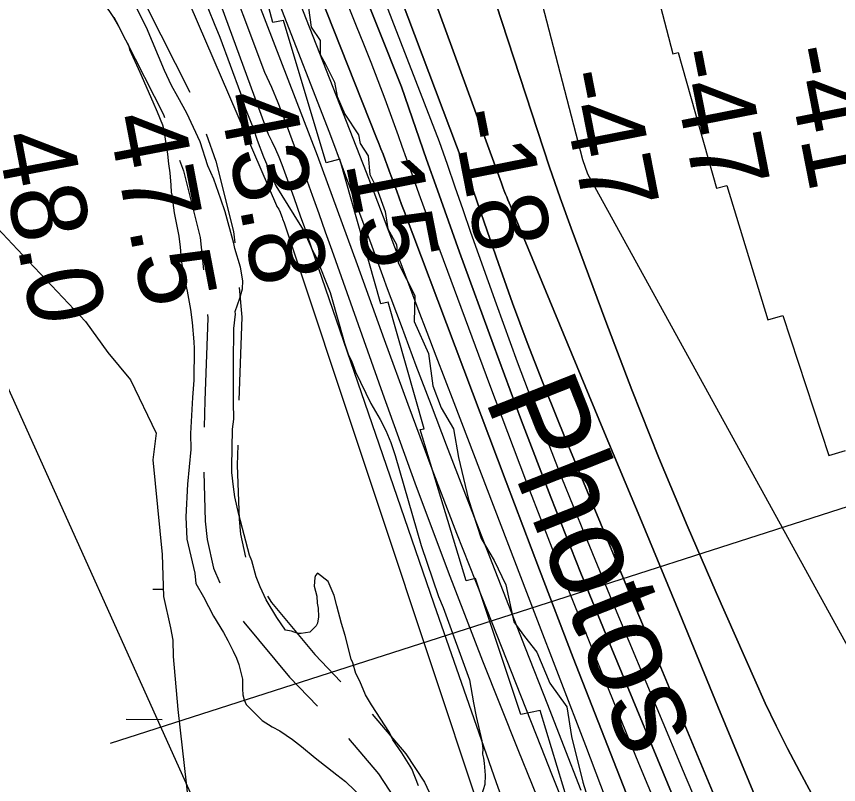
# Model space of a CAD drawing. Extents: x 3161665 to 3199565, y 885729 to 911164.
# Drawn here: x 3176382 to 3177112, y 893014 to 893695 of the extents above; entities that cross this region are included whole.
import ezdxf

# ---------------------------------------------------------------- set-up
doc = ezdxf.new("R2010")
doc.units = 0
for name, color, linetype in [('V-RIVR-EDGE', 7, 'Continuous'), ('V-RIVR-IDEN', 7, 'Continuous'), ('V-RIVR-RANG', 7, 'Continuous'), ('V-ROAD-CNTR', 7, 'Continuous'), ('V-RRAP-RVMT', 7, 'Continuous'), ('V-SITE-VEGE', 7, 'Continuous'), ('V-TOPO-DPTH', 7, 'Continuous'), ('V-TOPO-MAJR', 7, 'Continuous'), ('V-TOPO-MINR', 7, 'Continuous'), ('V-TOPO-WATR', 7, 'Continuous'), ('V-WETL-SWMP', 7, 'Continuous')]:
    doc.layers.add(name, color=color, linetype=linetype)

msp = doc.modelspace()

# ---------------------------------------------------------------- linework, layer by layer
at = {"layer": 'V-RIVR-EDGE'}
msp.add_lwpolyline([(3176641.22, 893703.05), (3176643.57, 893685.88), (3176651.64, 893673.94), (3176651.61, 893661.54), (3176656.36, 893652.94), (3176664.43, 893637.19), (3176666.78, 893624.31), (3176673.42, 893608.55), (3176685.77, 893590.4), (3176687.18, 893582.77), (3176694.31, 893571.78), (3176695.7, 893555.09), (3176701.87, 893542.67), (3176709.45, 893522.15), (3176711.79, 893506.88), (3176719.39, 893493.04), (3176720.78, 893476.82), (3176735.49, 893447.69), (3176734.96, 893424.8), (3176747.76, 893396.16), (3176751.51, 893367.54), (3176759.09, 893347.97), (3176770.01, 893329.34), (3176774.24, 893304.06), (3176783.21, 893266.84), (3176794.57, 893232), (3176805.96, 893212.42), (3176816.4, 893190.93), (3176823.47, 893158.01), (3176832.98, 893145.11), (3176843.91, 893131.26), (3176855.29, 893103.57), (3176870.5, 893082.55), (3176874.72, 893056.31), (3176884.64, 893015.75), (3176892.68, 892989.98)], dxfattribs=at)
at = {"layer": 'V-RIVR-RANG'}
msp.add_line((3176465.71, 893050.35), (3177322.46, 893325.99), dxfattribs=at)
at = {"layer": 'V-ROAD-CNTR'}
for points in [[(3176490.46, 893717.29), (3176497.28, 893704.73), (3176536, 893628.32)], [(3176468.49, 893694.88), (3176470.71, 893690.79), (3176512.52, 893608.28), (3176513.47, 893605.64)], [(3176550.51, 893591.11), (3176559.12, 893566.98), (3176574.75, 893504.51), (3176575.83, 893494.59)], [(3176526.91, 893567.97), (3176530.38, 893558.27), (3176545.14, 893499.22), (3176548.27, 893470.56)], [(3176579.84, 893454.8), (3176582.13, 893428.5), (3176579.4, 893354.96)], [(3176551.82, 893430.74), (3176552.08, 893427.75), (3176549.36, 893354.42), (3176548.85, 893330.81)], [(3176578.52, 893314.97), (3176578.14, 893297.13), (3176579.7, 893249.37), (3176581.09, 893235.88), (3176585.5, 893215.54)], [(3176548.33, 893290.82), (3176549.75, 893247.34), (3176551.42, 893231.16), (3176556.95, 893205.64), (3176562.57, 893192.69)], [(3176605.04, 893180.76), (3176608.36, 893175.39), (3176646.8, 893129.08), (3176670.09, 893105.02)], [(3176583.47, 893158.6), (3176583.94, 893157.83), (3176624.44, 893109.04), (3176649.26, 893083.4)], [(3176697.8, 893076.18), (3176727.62, 893041.12), (3176744.11, 893015.76), (3176754.36, 892994.38)], [(3176676.87, 893054.48), (3176703.52, 893023.14), (3176717.91, 893001.04), (3176731.94, 892971.75)]]:
    msp.add_lwpolyline(points, dxfattribs=at)
at = {"layer": 'V-RRAP-RVMT'}
for p, q in [((3176609.54, 893690.09), (3176577.55, 893814.21)), ((3176933.46, 893783), (3176964.43, 893662.23)), ((3176619.1, 893691.86), (3176609.54, 893690.09)), ((3176656.87, 893565.36), (3176619.1, 893691.86)), ((3176964.43, 893662.23), (3176969.2, 893663.46)), ((3176969.2, 893663.46), (3177003.33, 893543.13)), ((3176669.2, 893568.67), (3176656.87, 893565.36)), ((3176705.58, 893440.31), (3176669.2, 893568.67)), ((3177003.33, 893543.13), (3177012.55, 893545.5)), ((3177012.55, 893545.5), (3177048.64, 893426.23)), ((3176711.88, 893441.97), (3176705.58, 893440.31)), ((3176743.89, 893329.53), (3176711.88, 893441.97)), ((3177048.64, 893426.23), (3177061.99, 893429.92)), ((3177061.99, 893429.92), (3177103.02, 893305.7)), ((3176740.38, 893328.74), (3176743.89, 893329.53)), ((3176781.18, 893194.51), (3176740.38, 893328.74)), ((3177103.02, 893305.7), (3177117.64, 893310.16)), ((3176789.44, 893196.61), (3176781.18, 893194.51)), ((3176829.6, 893075.78), (3176789.44, 893196.61)), ((3176846.75, 893079.56), (3176829.6, 893075.78)), ((3176884.23, 892956.27), (3176846.75, 893079.56))]:
    msp.add_line(p, q, dxfattribs=at)
at = {"layer": 'V-SITE-VEGE'}
for p, q in [((3176459.68, 893707.05), (3176468.34, 893694.32)), ((3176468.34, 893694.32), (3176472.72, 893686.83)), ((3176472.72, 893686.83), (3176477.66, 893676.65)), ((3176477.66, 893676.65), (3176481.55, 893670.04)), ((3176481.55, 893670.04), (3176482.62, 893666.03)), ((3176482.62, 893666.03), (3176491.59, 893646.09)), ((3176491.59, 893646.09), (3176503.08, 893619.49)), ((3176503.08, 893619.49), (3176507.07, 893610.62)), ((3176507.07, 893610.62), (3176511.62, 893599.08)), ((3176511.62, 893599.08), (3176512.65, 893595.96)), ((3176512.65, 893595.96), (3176516.32, 893573.09)), ((3176516.32, 893573.09), (3176517.13, 893564.55)), ((3176517.13, 893564.55), (3176518.37, 893556.47)), ((3176518.37, 893556.47), (3176519.28, 893545.68)), ((3176519.28, 893545.68), (3176519.55, 893539.37)), ((3176519.55, 893539.37), (3176520.11, 893536.68)), ((3176520.11, 893536.68), (3176522.12, 893520.97)), ((3176522.12, 893520.97), (3176526.15, 893500.37)), ((3176526.15, 893500.37), (3176527.47, 893490.49)), ((3176527.47, 893490.49), (3176527.6, 893487.34)), ((3176527.6, 893487.34), (3176528.39, 893479.24)), ((3176528.39, 893479.24), (3176530.8, 893464.9)), ((3176530.8, 893464.9), (3176533.62, 893451.48)), ((3176533.62, 893451.48), (3176536.56, 893435.35)), ((3176536.56, 893435.35), (3176537.95, 893423.67)), ((3176537.95, 893423.67), (3176539.57, 893406.58)), ((3176539.57, 893406.58), (3176539.82, 893400.72)), ((3176539.82, 893400.72), (3176539.64, 893372.73)), ((3176539.64, 893372.73), (3176538.48, 893357.33)), ((3176538.48, 893357.33), (3176536.67, 893325.2)), ((3176536.67, 893325.2), (3176536.81, 893311.21)), ((3176536.81, 893311.21), (3176534.04, 893280.39)), ((3176534.04, 893280.39), (3176532.55, 893251.44)), ((3176532.55, 893251.44), (3176533.38, 893231.61)), ((3176533.38, 893231.61), (3176540.53, 893201.21)), ((3176540.53, 893201.21), (3176541.36, 893192.22)), ((3176541.36, 893192.22), (3176548.18, 893180.32)), ((3176548.18, 893180.32), (3176557.03, 893163.08)), ((3176557.03, 893163.08), (3176565.76, 893148.55)), ((3176565.76, 893148.55), (3176569.67, 893141.49)), ((3176569.67, 893141.49), (3176574.58, 893132.22)), ((3176574.58, 893132.22), (3176577.55, 893126.02)), ((3176577.55, 893126.02), (3176579.59, 893120.24)), ((3176579.59, 893120.24), (3176582.85, 893107.28)), ((3176582.85, 893107.28), (3176582.76, 893098.7)), ((3176582.76, 893098.7), (3176582.98, 893093.29)), ((3176582.98, 893093.29), (3176584.07, 893088.83)), ((3176584.07, 893088.83), (3176586.04, 893084.85)), ((3176586.04, 893084.85), (3176600.19, 893070.54)), ((3176600.19, 893070.54), (3176609, 893065.04)), ((3176609, 893065.04), (3176615.93, 893061.27)), ((3176615.93, 893061.27), (3176627.09, 893053.61)), ((3176627.09, 893053.61), (3176635.01, 893047.63)), ((3176635.01, 893047.63), (3176647.18, 893037.3)), ((3176647.18, 893037.3), (3176666.32, 893022.31)), ((3176666.32, 893022.31), (3176674.25, 893016.32)), ((3176674.25, 893016.32), (3176690.25, 893000.74))]:
    msp.add_line(p, q, dxfattribs=at)
for points in [[(3176574.78, 893352.98), (3176574.75, 893396.77), (3176575.12, 893409.43), (3176575.19, 893418.46), (3176576.46, 893431.15), (3176576.37, 893433.41), (3176580.38, 893445.31), (3176582.74, 893453.54), (3176582.89, 893460.77), (3176581.03, 893472.88), (3176575.82, 893489.36), (3176575.18, 893493.85), (3176567.23, 893521.96), (3176563.6, 893533.09), (3176557.43, 893550.89), (3176551.97, 893562.85), (3176545.2, 893584.24), (3176533.3, 893609.47), (3176525.47, 893624.04), (3176519.62, 893634.17), (3176513.65, 893647.47), (3176497.6, 893685.62), (3176495.16, 893690.03), (3176482.79, 893715.69)], [(3176547.41, 893714.34), (3176557.5, 893689.04), (3176562.52, 893677.06), (3176580.86, 893627.27), (3176585.5, 893613.47), (3176592.57, 893595.71), (3176595.71, 893585.45), (3176601.29, 893570.79), (3176612.3, 893545.07), (3176633.61, 893510.75), (3176637.01, 893505.03), (3176644.96, 893487.75), (3176647.89, 893482.46), (3176660.52, 893450.49), (3176668.47, 893422.38), (3176673.25, 893405.43), (3176676.86, 893394.74), (3176679.32, 893389.88), (3176682.89, 893380.1), (3176696.72, 893351.79), (3176704.99, 893337.69), (3176709.91, 893327.96), (3176714.42, 893317.32), (3176718.07, 893305.73), (3176741.29, 893225.9), (3176756.74, 893180.5), (3176760.76, 893170.74), (3176784.22, 893106.72), (3176787.79, 893086.1), (3176790.1, 893074.01), (3176795.07, 893052.55), (3176795.8, 893045.81), (3176795.56, 893040.83), (3176796.61, 893037.26), (3176797.26, 893032.78), (3176798.16, 893021.98), (3176797.6, 893013.83), (3176794.84, 893004.23)], [(3176738.96, 893012.72), (3176732.91, 893027.81), (3176724.19, 893041.89), (3176716.04, 893053.29), (3176713.05, 893059.94), (3176697.12, 893084.55), (3176691.78, 893093.35), (3176686.76, 893105.33), (3176683.3, 893112.41), (3176680.65, 893121.78), (3176679.17, 893124.88), (3176673.77, 893145.87), (3176670.61, 893156.57), (3176666.34, 893172.19), (3176664.15, 893181.58), (3176658.66, 893193.99), (3176649.32, 893201.27), (3176647.6, 893199.39), (3176646.77, 893197.55), (3176646.19, 893189.85), (3176648.82, 893180.93), (3176649.09, 893174.63), (3176649.73, 893170.14), (3176650.05, 893162.48), (3176649.38, 893157.03), (3176648.12, 893154.72), (3176645.96, 893152.37), (3176642.49, 893149.07), (3176634.87, 893147.84), (3176631.71, 893147.71), (3176626.21, 893149.74), (3176620.74, 893150.86), (3176613.06, 893161.83), (3176603.82, 893177.69), (3176598.37, 893189.2), (3176594.83, 893198.08), (3176591.07, 893212.36), (3176589.06, 893217.25), (3176579.42, 893253.41), (3176576.05, 893269.07), (3176574.77, 893278.04), (3176573.34, 893290.62), (3176573.13, 893295.58), (3176573.98, 893329.02), (3176574.95, 893338.09), (3176574.78, 893352.98)]]:
    msp.add_lwpolyline(points, dxfattribs=at)
at = {"layer": 'V-TOPO-DPTH'}
for points in [[(3176474.19, 894812.27), (3176539.01, 894548.12), (3176551.8, 894498.57), (3176565.37, 894449.24), (3176580.12, 894400.26), (3176595.65, 894351.5), (3176614.05, 894296.04), (3176621.17, 894275.25), (3176628.57, 894254.57), (3176855.03, 893561.59), (3176864.47, 893534.44), (3176874.25, 893507.41), (3176905.05, 893424.69), (3176928.25, 893364.03), (3176952.17, 893303.67), (3176977.16, 893243.75), (3177002.88, 893184.12), (3177037.17, 893106.53), (3177046.52, 893086.03), (3177056.18, 893065.69), (3177066.33, 893045.59), (3177076.79, 893025.64), (3177087.65, 893005.9)], [(3177087.65, 893005.9), (3177076.79, 893025.64), (3177066.33, 893045.59), (3177056.18, 893065.69), (3177046.52, 893086.03), (3177037.17, 893106.53), (3177002.88, 893184.12), (3176977.16, 893243.75), (3176952.17, 893303.67), (3176928.25, 893364.03), (3176905.05, 893424.69), (3176874.25, 893507.41), (3176864.47, 893534.44), (3176855.03, 893561.59), (3176628.57, 894254.57), (3176621.17, 894275.25), (3176614.05, 894296.04), (3176595.65, 894351.5), (3176580.12, 894400.26), (3176565.37, 894449.24), (3176551.8, 894498.57), (3176539.01, 894548.12), (3176474.19, 894812.27)], [(3176937.08, 892970.62), (3176906.53, 893048.4), (3176876.23, 893126.28), (3176846.32, 893204.31), (3176816.66, 893282.44), (3176726.17, 893522.54), (3176723.94, 893528.51), (3176721.72, 893534.48), (3176719.52, 893540.45), (3176717.34, 893546.44), (3176716.56, 893548.6), (3176714.77, 893553.5), (3176712.96, 893558.4), (3176711.13, 893563.28), (3176709.29, 893568.17), (3176707.42, 893573.04), (3176705.54, 893577.91), (3176703.64, 893582.77), (3176701.72, 893587.62), (3176454.57, 894211.21)], [(3176937.08, 892970.62), (3176906.53, 893048.4), (3176876.23, 893126.28), (3176846.32, 893204.31), (3176816.66, 893282.44), (3176726.17, 893522.54), (3176723.94, 893528.51), (3176721.72, 893534.48), (3176719.52, 893540.45), (3176717.34, 893546.44), (3176716.56, 893548.6), (3176714.77, 893553.5), (3176712.96, 893558.4), (3176711.13, 893563.28), (3176709.29, 893568.17), (3176707.42, 893573.04), (3176705.54, 893577.91), (3176703.64, 893582.77), (3176701.72, 893587.62), (3176454.57, 894211.21)], [(3176964.75, 893002.83), (3176910.27, 893134.05), (3176882.9, 893201.27), (3176856.14, 893268.72), (3176830.29, 893336.53), (3176805.05, 893404.57), (3176775.38, 893486.27), (3176765.51, 893513.67), (3176755.72, 893541.1), (3176746.07, 893568.58), (3176736.52, 893596.09), (3176723.83, 893632.92), (3176494.51, 894207.93)], [(3176494.51, 894207.93), (3176723.83, 893632.92), (3176736.52, 893596.09), (3176746.07, 893568.58), (3176755.72, 893541.1), (3176765.51, 893513.67), (3176775.38, 893486.27), (3176805.05, 893404.57), (3176830.29, 893336.53), (3176856.14, 893268.72), (3176882.9, 893201.27), (3176910.27, 893134.05), (3176964.75, 893002.83)], [(3176578.93, 894187.59), (3176812.57, 893547.36), (3176814.11, 893542.94), (3176814.95, 893540.75), (3176816.15, 893537.75), (3176817.2, 893535.17), (3176818.26, 893532.6), (3176819.32, 893530.02), (3176820.39, 893527.44), (3176902.55, 893329.53), (3176936.6, 893247.41), (3176970.61, 893165.28), (3177004.56, 893083.12), (3177038.47, 893000.94)], [(3177038.47, 893000.94), (3177004.56, 893083.12), (3176970.61, 893165.28), (3176936.6, 893247.41), (3176902.55, 893329.53), (3176820.39, 893527.44), (3176819.32, 893530.02), (3176818.26, 893532.6), (3176817.2, 893535.17), (3176816.15, 893537.75), (3176814.95, 893540.75), (3176814.11, 893542.94), (3176812.57, 893547.36), (3176578.93, 894187.59)], [(3176436.72, 894166.21), (3176659.83, 893591.97), (3176672.02, 893559.57), (3176684.15, 893527.15), (3176696.18, 893494.7), (3176708.16, 893462.23), (3176710.3, 893456.4), (3176723.39, 893421.03), (3176736.6, 893385.7), (3176749.99, 893350.44), (3176763.5, 893315.23), (3176775.09, 893285.27), (3176794.53, 893235.12), (3176814.02, 893185), (3176833.6, 893134.91), (3176853.22, 893084.84), (3176867.33, 893048.92), (3176882.96, 893008.8)], [(3176593.22, 894056.99), (3176785.41, 893546.84), (3176789.9, 893533.63), (3176794.44, 893520.44), (3176809.81, 893476.16), (3176822.36, 893440.95), (3176835.32, 893405.9), (3176848.86, 893371.07), (3176862.81, 893336.38), (3176867.26, 893325.56), (3176883.76, 893285.6), (3176900.31, 893245.65), (3176916.92, 893205.74), (3176933.58, 893165.84), (3176949.33, 893128.2), (3176970.07, 893078.55), (3176990.76, 893028.87), (3177011.39, 892979.17)], [(3177011.39, 892979.17), (3176990.76, 893028.87), (3176970.07, 893078.55), (3176949.33, 893128.2), (3176933.58, 893165.84), (3176916.92, 893205.74), (3176900.31, 893245.65), (3176883.76, 893285.6), (3176867.26, 893325.56), (3176862.81, 893336.38), (3176848.86, 893371.07), (3176835.32, 893405.9), (3176822.36, 893440.95), (3176809.81, 893476.16), (3176794.44, 893520.44), (3176789.9, 893533.63), (3176785.41, 893546.84), (3176593.22, 894056.99)]]:
    msp.add_lwpolyline(points, dxfattribs=at)
at = {"layer": 'V-TOPO-MAJR'}
for points in [[(3177266.38, 892869.65), (3176888.97, 893555.49), (3176884.77, 893568.13), (3176719.38, 894205.41), (3176712.92, 894236.95), (3176706.65, 894268.53), (3176700.65, 894300.16), (3176561.53, 894735.82), (3176550.46, 894770.02)], [(3176382.31, 894200.42), (3176605.45, 893591.02), (3176608.84, 893584.39), (3176612.03, 893577.66), (3176614.92, 893570.81), (3176617.61, 893563.87), (3176628.13, 893534.82), (3176631.24, 893526.17), (3176634.32, 893517.51), (3176637.36, 893508.83), (3176640.38, 893500.14), (3176726.22, 893250.61), (3176752.61, 893174.22), (3176779.12, 893097.87), (3176805.83, 893021.6), (3176832.67, 892945.36)]]:
    msp.add_lwpolyline(points, dxfattribs=at)
at = {"layer": 'V-TOPO-MINR'}
for points in [[(3177087.65, 893005.9), (3177076.79, 893025.64), (3177066.33, 893045.59), (3177056.18, 893065.69), (3177046.52, 893086.03), (3177037.17, 893106.53), (3177002.88, 893184.12), (3176977.16, 893243.75), (3176952.17, 893303.67), (3176928.25, 893364.03), (3176905.05, 893424.69), (3176874.25, 893507.41), (3176864.47, 893534.44), (3176855.03, 893561.59), (3176628.57, 894254.57), (3176621.17, 894275.25), (3176614.05, 894296.04), (3176595.65, 894351.5), (3176580.12, 894400.26), (3176565.37, 894449.24), (3176551.8, 894498.57), (3176539.01, 894548.12), (3176474.19, 894812.27)], [(3176180.84, 894761.9), (3176248.36, 894467.34), (3176259.04, 894422.27), (3176270.15, 894377.31), (3176281.93, 894332.52), (3176294.14, 894287.84), (3176303.62, 894254.1), (3176311.55, 894226.41), (3176612.77, 893527.63), (3176613.34, 893526.85), (3176614.88, 893524.42), (3176616.12, 893521.83), (3176616.47, 893520.93), (3176617.94, 893516.84), (3176618.35, 893515.67), (3176619.56, 893512.15), (3176762.91, 893082.18), (3176779.18, 893033.14), (3176795.37, 892984.08)], [(3176568.91, 892934.65), (3176340.59, 893441.26), (3176336.7, 893450.17), (3176332.96, 893459.12), (3176329.43, 893468.17), (3176326.05, 893477.27), (3176322.85, 893486.45), (3176319.75, 893495.65), (3176316.81, 893504.91), (3176313.97, 893514.2), (3176311.3, 893523.21), (3176307.05, 893536.99), (3176302.6, 893550.69), (3176297.85, 893564.29), (3176292.89, 893577.82), (3176188.35, 893853.51), (3176169.56, 893903.6), (3176151, 893953.77), (3176132.79, 894004.07), (3176114.82, 894054.46), (3176079.71, 894153.96), (3176079.49, 894154.66), (3176078.96, 894156.82), (3176062.34, 894249.64)], [(3176494.51, 894207.93), (3176723.83, 893632.92), (3176736.52, 893596.09), (3176746.07, 893568.58), (3176755.72, 893541.1), (3176765.51, 893513.67), (3176775.38, 893486.27), (3176805.05, 893404.57), (3176830.29, 893336.53), (3176856.14, 893268.72), (3176882.9, 893201.27), (3176910.27, 893134.05), (3176964.75, 893002.83)], [(3177038.47, 893000.94), (3177004.56, 893083.12), (3176970.61, 893165.28), (3176936.6, 893247.41), (3176902.55, 893329.53), (3176820.39, 893527.44), (3176819.32, 893530.02), (3176818.26, 893532.6), (3176817.2, 893535.17), (3176816.15, 893537.75), (3176814.95, 893540.75), (3176814.11, 893542.94), (3176812.57, 893547.36), (3176578.93, 894187.59)], [(3176447.2, 894182.97), (3176692.44, 893557.31), (3176697.54, 893544.04), (3176702.62, 893530.75), (3176707.67, 893517.46), (3176712.7, 893504.16), (3176717.71, 893490.85), (3176722.72, 893477.54), (3176727.74, 893464.23), (3176732.76, 893450.92), (3176738.42, 893435.91), (3176746.29, 893415.11), (3176754.19, 893394.31), (3176762.13, 893373.53), (3176770.09, 893352.76), (3176841.54, 893166.81), (3176864.28, 893107.55), (3176886.97, 893048.27), (3176909.61, 892988.97)], [(3176405.67, 894169.82), (3176602.22, 893646.03), (3176608.39, 893632.67), (3176614.05, 893619.08), (3176619.38, 893605.35), (3176638.48, 893553.24), (3176644.42, 893536.93), (3176650.33, 893520.61), (3176656.19, 893504.27), (3176662.02, 893487.92), (3176706.94, 893361.17), (3176735.72, 893281.63), (3176765.21, 893202.36), (3176795.75, 893123.49), (3176826.99, 893044.88), (3176915.91, 892825.39)], [(3176436.72, 894166.21), (3176659.83, 893591.97), (3176672.02, 893559.57), (3176684.15, 893527.15), (3176696.18, 893494.7), (3176708.16, 893462.23), (3176710.3, 893456.4), (3176723.39, 893421.03), (3176736.6, 893385.7), (3176749.99, 893350.44), (3176763.5, 893315.23), (3176775.09, 893285.27), (3176794.53, 893235.12), (3176814.02, 893185), (3176833.6, 893134.91), (3176853.22, 893084.84), (3176867.33, 893048.92), (3176882.96, 893008.8)], [(3176426.33, 894149.65), (3176649.02, 893572.21), (3176657.97, 893548.02), (3176666.86, 893523.81), (3176675.69, 893499.57), (3176684.46, 893475.31), (3176708.43, 893408.74), (3176729.42, 893351.29), (3176750.77, 893293.97), (3176772.67, 893236.86), (3176794.92, 893179.88), (3176847.08, 893048.17), (3176857.6, 893021.66), (3176868.14, 892995.16)], [(3176573.81, 894057.29), (3176757.34, 893584.36), (3176764.17, 893564.2), (3176771.07, 893544.07), (3176778.07, 893523.97), (3176785.14, 893503.89), (3176807.68, 893440.41), (3176826.47, 893388.76), (3176845.78, 893337.32), (3176865.87, 893286.17), (3176886.48, 893235.23), (3176910.48, 893177.19), (3176925.46, 893141.07), (3176940.47, 893104.96), (3176955.55, 893068.88), (3176970.66, 893032.81), (3176972.86, 893027.57), (3176986.88, 892994.13)], [(3176593.22, 894056.99), (3176785.41, 893546.84), (3176789.9, 893533.63), (3176794.44, 893520.44), (3176809.81, 893476.16), (3176822.36, 893440.95), (3176835.32, 893405.9), (3176848.86, 893371.07), (3176862.81, 893336.38), (3176867.26, 893325.56), (3176883.76, 893285.6), (3176900.31, 893245.65), (3176916.92, 893205.74), (3176933.58, 893165.84), (3176949.33, 893128.2), (3176970.07, 893078.55), (3176990.76, 893028.87), (3177011.39, 892979.17)], [(3176677.17, 893703.29), (3176683.67, 893687.16), (3176690.11, 893670.99), (3176696.49, 893654.81), (3176702.76, 893638.58), (3176708.92, 893622.31), (3176714.91, 893605.98), (3176720.79, 893589.61), (3176724.14, 893580.13), (3176731.67, 893559), (3176739.26, 893537.9), (3176746.95, 893516.83), (3176754.71, 893495.79), (3176801.92, 893368.64), (3176833.84, 893284.24), (3176866.41, 893200.09), (3176899.97, 893116.34), (3176934.18, 893032.84), (3177018.27, 892831.06)]]:
    msp.add_lwpolyline(points, dxfattribs=at)
at = {"layer": 'V-TOPO-WATR'}
msp.add_lwpolyline([(3176454.57, 894211.21), (3176701.72, 893587.62), (3176703.64, 893582.77), (3176705.54, 893577.91), (3176707.42, 893573.04), (3176709.29, 893568.17), (3176711.13, 893563.28), (3176712.96, 893558.4), (3176714.77, 893553.5), (3176716.56, 893548.6), (3176717.34, 893546.44), (3176719.52, 893540.45), (3176721.72, 893534.48), (3176723.94, 893528.51), (3176726.17, 893522.54), (3176816.66, 893282.44), (3176846.32, 893204.31), (3176876.23, 893126.28), (3176906.53, 893048.4), (3176937.08, 892970.62)], dxfattribs=at)
at = {"layer": 'V-WETL-SWMP'}
for p, q in [((3176357.94, 893515.44), (3176383, 893488.42)), ((3176383, 893488.42), (3176443.42, 893424.53)), ((3176443.42, 893424.53), (3176463.34, 893397.3)), ((3176463.34, 893397.3), (3176483.35, 893372.83)), ((3176483.35, 893372.83), (3176506.29, 893325.56)), ((3176506.29, 893325.56), (3176503.14, 893301.9)), ((3176503.14, 893301.9), (3176511.41, 893218.03)), ((3176511.41, 893218.03), (3176512.59, 893180.52)), ((3176503.25, 893187.01), (3176512.39, 893186.98)), ((3176512.59, 893180.52), (3176518.89, 893152.91)), ((3176518.89, 893152.91), (3176520.94, 893141.73)), ((3176520.94, 893141.73), (3176521.35, 893127.31)), ((3176521.35, 893127.31), (3176525.51, 893080.24)), ((3176525.51, 893080.24), (3176584.95, 892548.78)), ((3176479.52, 893071.64), (3176511.52, 893071.55))]:
    msp.add_line(p, q, dxfattribs=at)

# ---------------------------------------------------------------- texts
at = {"layer": 'V-RIVR-IDEN'}
msp.add_text('Photos', height=83, rotation=291.59001, dxfattribs=at).set_placement((3176797.06, 893356.41))
at = {"layer": 'V-RIVR-RANG'}
for s, rotation, p in [('-47', 281.12028, (3176960.53, 893663.2)), ('-41', 281.12028, (3177061.9, 893665.94)), ('-47', 281.12028, (3176862.36, 893644.16)), ('43.8', 280.83833, (3176561.12, 893624.31)), ('-18', 281.12028, (3176767.24, 893609.58)), ('47.5', 280.83833, (3176462.95, 893605.27)), ('48.0', 280.83833, (3176364.23, 893589.07)), ('15', 281.12028, (3176673.96, 893565.69))]:
    msp.add_text(s, height=67, rotation=rotation, dxfattribs=at).set_placement(p)

doc.saveas('drawing.dxf')
